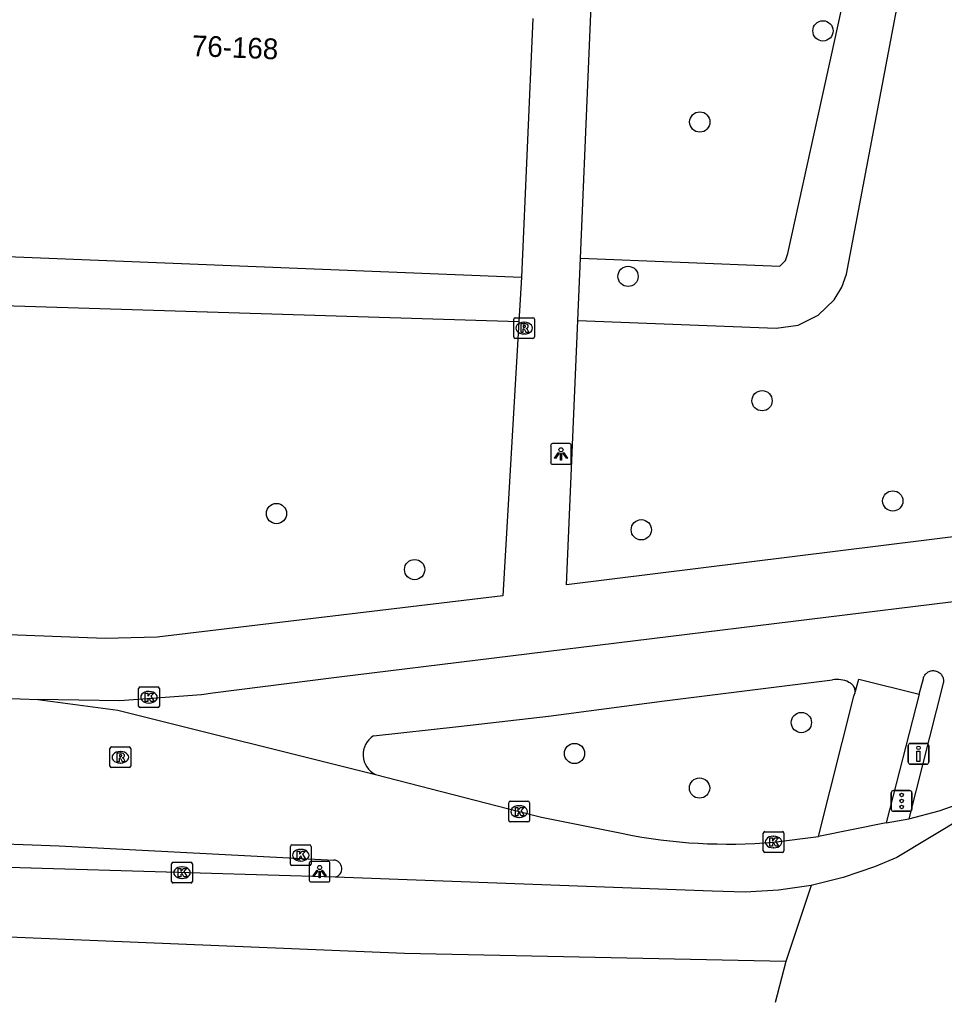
# Model space of a CAD drawing. Extents: x 161253 to 161848, y 384872 to 385383.
# Drawn here: x 161691.79 to 161736.4, y 384872.21 to 384919.64 of the extents above; entities that cross this region are included whole.
import ezdxf

# ---------------------------------------------------------------- set-up
doc = ezdxf.new("R2010")
doc.units = 0
for name, color, linetype in [('IMGEO_Boom', 7, 'Continuous'), ('IMGEO_Drukknoppaal', 7, 'Continuous'), ('IMGEO_Groenvoorziening', 7, 'Continuous'), ('IMGEO_Kolk', 7, 'Continuous'), ('IMGEO_Lichtpunt', 7, 'Continuous'), ('IMGEO_Pand', 7, 'Continuous'), ('IMGEO_Pand_nummerreeks', 7, 'Continuous'), ('IMGEO_Rijbaan_lokaal_open', 7, 'Continuous'), ('IMGEO_Rijbaan_regionaal_gesloten', 7, 'Continuous'), ('IMGEO_Rioolput', 7, 'Continuous'), ('IMGEO_Verkeersregelinstallatiepaal', 7, 'Continuous'), ('IMGEO_Voetpad_gesloten', 7, 'Continuous'), ('IMGEO_Voetpad_open', 7, 'Continuous')]:
    doc.layers.add(name, color=color, linetype=linetype)

msp = doc.modelspace()

# ---------------------------------------------------------------- linework, layer by layer
at = {"layer": 'IMGEO_Boom'}
for centre in [(161730.544, 384919.094), (161724.601, 384914.698), (161721.141, 384907.247), (161727.606, 384901.246), (161733.913, 384896.406), (161704.18, 384895.799), (161721.78, 384895.018), (161710.846, 384893.095), (161729.501, 384885.713), (161718.558, 384884.22), (161724.59, 384882.552)]:
    msp.add_circle(centre, 0.489, dxfattribs=at)
at = {"layer": 'IMGEO_Drukknoppaal'}
for p, q in [((161734.755, 384884.702), (161735.545, 384884.702)), ((161735.545, 384884.702), (161734.755, 384884.702)), ((161734.655, 384883.802), (161734.655, 384884.602)), ((161734.655, 384884.602), (161734.655, 384883.802)), ((161735.645, 384884.602), (161735.645, 384883.802)), ((161735.645, 384883.802), (161735.645, 384884.602)), ((161735.545, 384883.702), (161734.755, 384883.702)), ((161734.755, 384883.702), (161735.545, 384883.702))]:
    msp.add_line(p, q, dxfattribs=at)
msp.add_lwpolyline([(161735.225, 384884.327), (161735.225, 384883.827), (161735.075, 384883.827), (161735.075, 384884.327), (161735.225, 384884.327)], dxfattribs=at)
msp.add_circle((161735.15, 384884.492), 0.085, dxfattribs=at)
for centre, start, end in [((161734.755, 384884.602), 90, 180), ((161734.755, 384884.602), 90, 180), ((161735.545, 384884.602), 0, 90), ((161735.545, 384884.602), 360, 90), ((161734.755, 384883.802), 180, 270), ((161734.755, 384883.802), 180, 270), ((161735.545, 384883.802), 270, 0), ((161735.545, 384883.802), 270, 0)]:
    msp.add_arc(centre, 0.1, start, end, dxfattribs=at)
at = {"layer": 'IMGEO_Groenvoorziening'}
for points in [[(161718.843, 384908.119), (161728.459, 384907.746), (161728.73, 384908.015), (161728.849, 384908.352), (161732.373, 384924.372)], [(161718.716, 384905.121), (161728.292, 384904.75), (161729.354, 384904.9), (161730.318, 384905.37), (161731.089, 384906.116), (161731.458, 384906.73), (161731.678, 384907.354), (161734.799, 384923.838)], [(161715.871, 384905.05), (161685.799, 384905.981)]]:
    msp.add_lwpolyline(points, dxfattribs=at)
at = {"layer": 'IMGEO_Kolk'}
for p, q in [((161697.529, 384886.507), (161697.529, 384887.359)), ((161697.604, 384887.433), (161698.456, 384887.433)), ((161698.017, 384887.213), (161698.042, 384887.213)), ((161698.53, 384887.359), (161698.53, 384886.507)), ((161698.04, 384886.653), (161698.015, 384886.653)), ((161698.456, 384886.433), (161697.604, 384886.433)), ((161715.385, 384880.99), (161715.385, 384881.842)), ((161715.46, 384881.916), (161716.312, 384881.916)), ((161716.386, 384881.842), (161716.386, 384880.99)), ((161715.873, 384881.696), (161715.898, 384881.696)), ((161716.312, 384880.916), (161715.46, 384880.916)), ((161715.896, 384881.136), (161715.871, 384881.136)), ((161727.736, 384880.446), (161728.588, 384880.446)), ((161727.661, 384879.52), (161727.661, 384880.372)), ((161728.149, 384880.226), (161728.174, 384880.226)), ((161728.662, 384880.372), (161728.662, 384879.52)), ((161704.85, 384878.884), (161704.85, 384879.736)), ((161704.925, 384879.81), (161705.777, 384879.81)), ((161705.338, 384879.59), (161705.363, 384879.59)), ((161705.851, 384879.736), (161705.851, 384878.884)), ((161728.588, 384879.446), (161727.736, 384879.446)), ((161728.172, 384879.666), (161728.147, 384879.666)), ((161699.196, 384878.969), (161700.048, 384878.969)), ((161705.361, 384879.03), (161705.336, 384879.03)), ((161699.121, 384878.043), (161699.121, 384878.895)), ((161699.609, 384878.749), (161699.634, 384878.749)), ((161700.122, 384878.895), (161700.122, 384878.043)), ((161705.777, 384878.81), (161704.925, 384878.81)), ((161699.632, 384878.189), (161699.607, 384878.189)), ((161700.048, 384877.969), (161699.196, 384877.969))]:
    msp.add_line(p, q, dxfattribs=at)
for points in [[(161697.529, 384886.507), (161697.529, 384887.359)], [(161697.604, 384887.433), (161698.456, 384887.433)], [(161697.85, 384887.133), (161697.973, 384887.133), (161697.973, 384886.982), (161698.103, 384887.133), (161698.267, 384887.133), (161698.121, 384886.982), (161698.274, 384886.733), (161698.122, 384886.733), (161698.037, 384886.897), (161697.973, 384886.83), (161697.973, 384886.733), (161697.85, 384886.733), (161697.85, 384887.133)], [(161698.53, 384887.359), (161698.53, 384886.507)], [(161698.456, 384886.433), (161697.604, 384886.433)], [(161715.385, 384880.99), (161715.385, 384881.842)], [(161715.46, 384881.916), (161716.312, 384881.916)], [(161716.386, 384881.842), (161716.386, 384880.99)], [(161715.706, 384881.616), (161715.829, 384881.616), (161715.829, 384881.465), (161715.959, 384881.616), (161716.123, 384881.616), (161715.977, 384881.465), (161716.13, 384881.216), (161715.978, 384881.216), (161715.893, 384881.38), (161715.829, 384881.313), (161715.829, 384881.216), (161715.706, 384881.216), (161715.706, 384881.616)], [(161716.312, 384880.916), (161715.46, 384880.916)], [(161727.736, 384880.446), (161728.588, 384880.446)], [(161727.661, 384879.52), (161727.661, 384880.372)], [(161727.982, 384880.146), (161728.105, 384880.146), (161728.105, 384879.995), (161728.235, 384880.146), (161728.399, 384880.146), (161728.253, 384879.995), (161728.406, 384879.746), (161728.254, 384879.746), (161728.169, 384879.91), (161728.105, 384879.843), (161728.105, 384879.746), (161727.982, 384879.746), (161727.982, 384880.146)], [(161728.662, 384880.372), (161728.662, 384879.52)], [(161704.85, 384878.884), (161704.85, 384879.736)], [(161704.925, 384879.81), (161705.777, 384879.81)], [(161705.171, 384879.51), (161705.294, 384879.51), (161705.294, 384879.359), (161705.424, 384879.51), (161705.588, 384879.51), (161705.442, 384879.359), (161705.595, 384879.11), (161705.443, 384879.11), (161705.358, 384879.274), (161705.294, 384879.207), (161705.294, 384879.11), (161705.171, 384879.11), (161705.171, 384879.51)], [(161705.851, 384879.736), (161705.851, 384878.884)], [(161728.588, 384879.446), (161727.736, 384879.446)], [(161699.196, 384878.969), (161700.048, 384878.969)], [(161699.121, 384878.043), (161699.121, 384878.895)], [(161699.442, 384878.669), (161699.565, 384878.669), (161699.565, 384878.518), (161699.695, 384878.669), (161699.859, 384878.669), (161699.713, 384878.518), (161699.866, 384878.269), (161699.714, 384878.269), (161699.629, 384878.433), (161699.565, 384878.366), (161699.565, 384878.269), (161699.442, 384878.269), (161699.442, 384878.669)], [(161700.122, 384878.895), (161700.122, 384878.043)], [(161705.777, 384878.81), (161704.925, 384878.81)], [(161700.048, 384877.969), (161699.196, 384877.969)]]:
    msp.add_lwpolyline(points, dxfattribs=at)
for centre, start, end in [((161697.606, 384887.357), 91.552, 178.448), ((161697.606, 384887.357), 91.552, 178.448), ((161698.454, 384887.357), 1.552, 88.448), ((161698.454, 384887.357), 1.552, 88.448), ((161697.606, 384886.509), 181.552, 268.448), ((161697.606, 384886.509), 181.552, 268.448), ((161698.454, 384886.509), 271.552, 358.448), ((161698.454, 384886.509), 271.552, 358.448), ((161715.462, 384881.84), 91.552, 178.448), ((161715.462, 384881.84), 91.552, 178.448), ((161716.31, 384881.84), 1.552, 88.448), ((161716.31, 384881.84), 1.552, 88.448), ((161715.462, 384880.992), 181.552, 268.448), ((161715.462, 384880.992), 181.552, 268.448), ((161716.31, 384880.992), 271.552, 358.448), ((161716.31, 384880.992), 271.552, 358.448), ((161727.738, 384880.37), 91.552, 178.448), ((161727.738, 384880.37), 91.552, 178.448), ((161728.586, 384880.37), 1.552, 88.448), ((161728.586, 384880.37), 1.552, 88.448), ((161704.927, 384879.734), 91.552, 178.448), ((161704.927, 384879.734), 91.552, 178.448), ((161705.775, 384879.734), 1.552, 88.448), ((161705.775, 384879.734), 1.552, 88.448), ((161727.738, 384879.522), 181.552, 268.448), ((161727.738, 384879.522), 181.552, 268.448), ((161728.586, 384879.522), 271.552, 358.448), ((161728.586, 384879.522), 271.552, 358.448), ((161699.198, 384878.893), 91.552, 178.448), ((161699.198, 384878.893), 91.552, 178.448), ((161700.046, 384878.893), 1.552, 88.448), ((161700.046, 384878.893), 1.552, 88.448), ((161704.927, 384878.886), 181.552, 268.448), ((161704.927, 384878.886), 181.552, 268.448), ((161705.775, 384878.886), 271.552, 358.448), ((161705.775, 384878.886), 271.552, 358.448), ((161699.198, 384878.045), 181.552, 268.448), ((161699.198, 384878.045), 181.552, 268.448), ((161700.046, 384878.045), 271.552, 358.448), ((161700.046, 384878.045), 271.552, 358.448)]:
    msp.add_arc(centre, 0.0765, start, end, dxfattribs=at)
for centre, major_axis, ratio, start_param, end_param in [((161698.016, 384886.933), (-0.387, 0.002), 0.722429, 4.712389, 7.853982), ((161698.041, 384886.933), (-0.39, 0.002), 0.717154, 1.570796, 4.712389), ((161715.872, 384881.416), (-0.387, 0.002), 0.722429, 4.712389, 7.853982), ((161715.897, 384881.416), (-0.39, 0.002), 0.717154, 1.570796, 4.712389), ((161728.148, 384879.946), (-0.387, 0.002), 0.722429, 4.712389, 7.853982), ((161728.173, 384879.946), (-0.39, 0.002), 0.717154, 1.570796, 4.712389), ((161705.337, 384879.31), (-0.387, 0.002), 0.722429, 4.712389, 7.853982), ((161705.362, 384879.31), (-0.39, 0.002), 0.717154, 1.570796, 4.712389), ((161699.608, 384878.469), (-0.387, 0.002), 0.722429, 4.712389, 7.853982), ((161699.633, 384878.469), (-0.39, 0.002), 0.717154, 1.570796, 4.712389)]:
    msp.add_ellipse(centre, major_axis=major_axis, ratio=ratio, start_param=start_param, end_param=end_param, dxfattribs=at)
at = {"layer": 'IMGEO_Lichtpunt'}
for p, q in [((161717.408, 384899.079), (161717.408, 384898.272)), ((161717.408, 384899.079), (161717.408, 384898.272)), ((161718.31, 384899.174), (161717.502, 384899.174)), ((161718.31, 384899.174), (161717.502, 384899.174)), ((161718.404, 384898.272), (161718.404, 384899.079)), ((161718.404, 384898.272), (161718.404, 384899.079)), ((161717.502, 384898.178), (161718.31, 384898.178)), ((161717.502, 384898.178), (161718.31, 384898.178)), ((161706.665, 384879.014), (161705.857, 384879.014)), ((161706.665, 384879.014), (161705.857, 384879.014)), ((161705.763, 384878.919), (161705.763, 384878.112)), ((161705.763, 384878.919), (161705.763, 384878.112)), ((161706.759, 384878.112), (161706.759, 384878.919)), ((161706.759, 384878.112), (161706.759, 384878.919)), ((161705.857, 384878.018), (161706.665, 384878.018)), ((161705.857, 384878.018), (161706.665, 384878.018))]:
    msp.add_line(p, q, dxfattribs=at)
for points in [[(161717.782, 384898.743), (161717.821, 384898.715), (161717.633, 384898.453), (161717.595, 384898.48), (161717.782, 384898.743)], [(161717.884, 384898.695), (161717.931, 384898.695), (161717.931, 384898.373), (161717.884, 384898.373), (161717.884, 384898.695)], [(161717.994, 384898.715), (161718.032, 384898.742), (161718.219, 384898.48), (161718.18, 384898.452), (161717.994, 384898.715)], [(161706.137, 384878.583), (161706.176, 384878.555), (161705.988, 384878.293), (161705.95, 384878.32), (161706.137, 384878.583)], [(161706.239, 384878.535), (161706.286, 384878.535), (161706.286, 384878.213), (161706.239, 384878.213), (161706.239, 384878.535)], [(161706.349, 384878.555), (161706.387, 384878.582), (161706.574, 384878.32), (161706.535, 384878.292), (161706.349, 384878.555)]]:
    msp.add_lwpolyline(points, dxfattribs=at)
for centre in [(161717.907, 384898.877), (161706.262, 384878.717)]:
    msp.add_circle(centre, 0.0994, dxfattribs=at)
for centre, start, end in [((161717.502, 384899.079), 90, 180), ((161717.502, 384899.079), 90, 180), ((161718.31, 384899.079), 0, 90), ((161718.31, 384899.079), 0, 90), ((161717.502, 384898.272), 180, 270), ((161717.502, 384898.272), 180, 270), ((161718.31, 384898.272), 270, 0), ((161718.31, 384898.272), 270, 360), ((161705.857, 384878.919), 90, 180), ((161705.857, 384878.919), 90, 180), ((161706.665, 384878.919), 0, 90), ((161706.665, 384878.919), 0, 90), ((161705.857, 384878.112), 180, 270), ((161705.857, 384878.112), 180, 270), ((161706.665, 384878.112), 270, 0), ((161706.665, 384878.112), 270, 360)]:
    msp.add_arc(centre, 0.0946, start, end, dxfattribs=at)
at = {"layer": 'IMGEO_Pand'}
for points in [[(161716.555, 384919.692), (161715.997, 384907.204)], [(161689.171, 384908.286), (161715.997, 384907.204)]]:
    msp.add_lwpolyline(points, dxfattribs=at)
at = {"layer": 'IMGEO_Rijbaan_lokaal_open'}
for points in [[(161662.403, 384887.976), (161663.754, 384887.928), (161666.228, 384887.818), (161692.66, 384886.829)], [(161692.66, 384886.829), (161696.52, 384886.316), (161708.962, 384883.201)], [(161734.693, 384881.066), (161736.146, 384881.444), (161737.56, 384881.951), (161738.922, 384882.582), (161740.223, 384883.332), (161741.028, 384883.879)], [(161708.962, 384883.201), (161715.882, 384881.415), (161716.973, 384881.138), (161720.912, 384880.351)], [(161662.143, 384880.926), (161667.54, 384880.734), (161693.704, 384879.755), (161706.945, 384879.077)], [(161733.587, 384880.868), (161730.33, 384880.216)], [(161733.587, 384880.868), (161734.693, 384881.066)], [(161728.163, 384879.945), (161730.33, 384880.216)]]:
    msp.add_lwpolyline(points, dxfattribs=at)
for centre, radius, start, end in [((161725.935, 384905.102), 25.256, 258.5288, 275.0616), ((161706.915, 384878.659), 0.419, 284.714, 85.838)]:
    msp.add_arc(centre, radius, start, end, dxfattribs=at)
at = {"layer": 'IMGEO_Rijbaan_regionaal_gesloten'}
for points in [[(161741.028, 384883.879), (161740.405, 384883.372), (161737.347, 384881.144), (161734.102, 384879.199), (161733.037, 384878.743), (161731.524, 384878.23), (161729.972, 384877.854)], [(161707.021, 384878.254), (161684.154, 384878.919), (161672.75, 384879.376), (161659.227, 384879.962), (161648.353, 384880.446)], [(161728.753, 384874.183), (161710.356, 384874.561), (161646.491, 384877.202), (161622.338, 384877.882), (161608.73, 384878.956), (161597.451, 384878.956), (161580.262, 384879.852), (161565.402, 384878.956), (161563.138, 384878.938)], [(161729.972, 384877.854), (161728.392, 384877.617), (161726.797, 384877.523), (161725.2, 384877.572), (161707.021, 384878.254)], [(161729.972, 384877.854), (161728.753, 384874.183)], [(161728.753, 384874.183), (161728.756, 384874.183), (161728.245, 384872.208)]]:
    msp.add_lwpolyline(points, dxfattribs=at)
at = {"layer": 'IMGEO_Rioolput'}
for p, q in [((161715.627, 384904.325), (161715.627, 384905.177)), ((161715.702, 384905.251), (161716.554, 384905.251)), ((161716.628, 384905.177), (161716.628, 384904.325)), ((161716.115, 384905.031), (161716.14, 384905.031)), ((161716.554, 384904.251), (161715.702, 384904.251)), ((161716.138, 384904.471), (161716.113, 384904.471)), ((161696.148, 384883.61), (161696.148, 384884.462)), ((161696.223, 384884.536), (161697.075, 384884.536)), ((161696.636, 384884.316), (161696.661, 384884.316)), ((161697.149, 384884.462), (161697.149, 384883.61)), ((161696.659, 384883.756), (161696.634, 384883.756)), ((161697.075, 384883.536), (161696.223, 384883.536))]:
    msp.add_line(p, q, dxfattribs=at)
for points in [[(161715.627, 384904.325), (161715.627, 384905.177)], [(161715.702, 384905.251), (161716.554, 384905.251)], [(161716.628, 384905.177), (161716.628, 384904.325)], [(161716.216, 384904.949), (161715.964, 384904.951), (161715.964, 384904.551)], [(161715.964, 384904.551), (161716.088, 384904.551), (161716.088, 384904.713), (161716.099, 384904.713)], [(161716.142, 384904.87), (161716.088, 384904.87), (161716.088, 384904.789)], [(161716.088, 384904.789), (161716.14, 384904.789)], [(161716.146, 384904.684), (161716.217, 384904.551), (161716.357, 384904.551), (161716.292, 384904.677)], [(161716.554, 384904.251), (161715.702, 384904.251)], [(161696.148, 384883.61), (161696.148, 384884.462)], [(161696.223, 384884.536), (161697.075, 384884.536)], [(161696.737, 384884.234), (161696.485, 384884.236), (161696.485, 384883.836)], [(161697.149, 384884.462), (161697.149, 384883.61)], [(161696.485, 384883.836), (161696.609, 384883.836), (161696.609, 384883.998), (161696.62, 384883.998)], [(161696.663, 384884.155), (161696.609, 384884.155), (161696.609, 384884.074)], [(161696.609, 384884.074), (161696.661, 384884.074)], [(161696.667, 384883.969), (161696.738, 384883.836), (161696.878, 384883.836), (161696.813, 384883.962)], [(161697.075, 384883.536), (161696.223, 384883.536)]]:
    msp.add_lwpolyline(points, dxfattribs=at)
for centre, radius, start, end in [((161715.704, 384905.175), 0.0765, 91.552, 178.448), ((161715.704, 384905.175), 0.0765, 91.552, 178.448), ((161716.552, 384905.175), 0.0765, 1.552, 88.448), ((161716.552, 384905.175), 0.0765, 1.552, 88.448), ((161716.098, 384904.66), 0.0533, 26.0293, 88.6989), ((161716.124, 384904.978), 0.19, 274.7715, 282.9687), ((161716.148, 384904.774), 0.0964, 77.0061, 93.1865), ((161716.162, 384904.831), 0.0378, 276.6634, 79.6772), ((161716.215, 384904.839), 0.109, 350.3612, 89.416), ((161716.213, 384904.839), 0.112, 277.5842, 350.9817), ((161716.197, 384904.624), 0.108, 29.5134, 73.7905), ((161715.704, 384904.327), 0.0765, 181.552, 268.448), ((161715.704, 384904.327), 0.0765, 181.552, 268.448), ((161716.552, 384904.327), 0.0765, 271.552, 358.448), ((161716.552, 384904.327), 0.0765, 271.552, 358.448), ((161696.225, 384884.46), 0.0765, 91.552, 178.448), ((161696.225, 384884.46), 0.0765, 91.552, 178.448), ((161696.736, 384884.124), 0.109, 350.3612, 89.416), ((161697.073, 384884.46), 0.0765, 1.552, 88.448), ((161697.073, 384884.46), 0.0765, 1.552, 88.448), ((161696.619, 384883.945), 0.0533, 26.0293, 88.6989), ((161696.645, 384884.263), 0.19, 274.7715, 282.9687), ((161696.669, 384884.059), 0.0964, 77.0061, 93.1865), ((161696.683, 384884.116), 0.0378, 276.6634, 79.6772), ((161696.734, 384884.124), 0.112, 277.5842, 350.9817), ((161696.718, 384883.909), 0.108, 29.5134, 73.7905), ((161696.225, 384883.612), 0.0765, 181.552, 268.448), ((161696.225, 384883.612), 0.0765, 181.552, 268.448), ((161697.073, 384883.612), 0.0765, 271.552, 358.448), ((161697.073, 384883.612), 0.0765, 271.552, 358.448)]:
    msp.add_arc(centre, radius, start, end, dxfattribs=at)
for centre, major_axis, ratio, start_param, end_param in [((161716.114, 384904.751), (-0.387, 0.002), 0.722429, 4.712389, 7.853982), ((161716.139, 384904.751), (-0.39, 0.002), 0.717154, 1.570796, 4.712389), ((161696.635, 384884.036), (-0.387, 0.002), 0.722429, 4.712389, 7.853982), ((161696.66, 384884.036), (-0.39, 0.002), 0.717154, 1.570796, 4.712389)]:
    msp.add_ellipse(centre, major_axis=major_axis, ratio=ratio, start_param=start_param, end_param=end_param, dxfattribs=at)
at = {"layer": 'IMGEO_Verkeersregelinstallatiepaal'}
for p, q in [((161733.842, 384881.528), (161733.842, 384882.328)), ((161733.842, 384882.328), (161733.842, 384881.528)), ((161733.942, 384882.428), (161734.732, 384882.428)), ((161734.732, 384882.428), (161733.942, 384882.428)), ((161734.832, 384882.328), (161734.832, 384881.528)), ((161734.832, 384881.528), (161734.832, 384882.328)), ((161734.732, 384881.428), (161733.942, 384881.428)), ((161733.942, 384881.428), (161734.732, 384881.428))]:
    msp.add_line(p, q, dxfattribs=at)
for centre in [(161734.337, 384882.218), (161734.337, 384881.928), (161734.337, 384881.638)]:
    msp.add_circle(centre, 0.085, dxfattribs=at)
for centre, start, end in [((161733.942, 384882.328), 90, 180), ((161733.942, 384882.328), 90, 180), ((161734.732, 384882.328), 0, 90), ((161734.732, 384882.328), 360, 90), ((161733.942, 384881.528), 180, 270), ((161733.942, 384881.528), 180, 270), ((161734.732, 384881.528), 270, 0), ((161734.732, 384881.528), 270, 0)]:
    msp.add_arc(centre, 0.1, start, end, dxfattribs=at)
at = {"layer": 'IMGEO_Voetpad_gesloten'}
for points in [[(161737.507, 384891.623), (161707.082, 384887.89), (161701.116, 384887.126), (161700.566, 384887.057), (161696.618, 384886.766), (161692.66, 384886.829)], [(161735.193, 384887.09), (161735.387, 384887.842), (161735.401, 384887.889), (161735.417, 384887.93), (161735.437, 384887.969), (161735.461, 384888.007), (161735.487, 384888.042), (161735.517, 384888.074), (161735.55, 384888.104), (161735.585, 384888.131), (161735.622, 384888.154), (161735.661, 384888.174), (161735.702, 384888.191), (161735.744, 384888.203), (161735.787, 384888.212), (161735.831, 384888.218), (161735.875, 384888.219), (161735.919, 384888.216), (161735.962, 384888.209), (161736.005, 384888.199), (161736.046, 384888.184), (161736.087, 384888.166), (161736.125, 384888.145), (161736.161, 384888.12), (161736.195, 384888.092), (161736.227, 384888.061), (161736.255, 384888.027), (161736.28, 384887.991), (161736.302, 384887.953), (161736.321, 384887.913), (161736.336, 384887.872), (161736.347, 384887.829), (161736.354, 384887.786), (161736.357, 384887.742), (161736.357, 384887.698), (161736.352, 384887.654), (161736.344, 384887.611), (161734.693, 384881.066)], [(161708.857, 384885.071), (161712.964, 384885.53), (161717.311, 384886.019), (161722.902, 384886.762), (161731.009, 384887.772)], [(161731.781, 384887.665), (161731.795, 384887.659), (161731.834, 384887.64), (161731.872, 384887.617), (161731.907, 384887.59), (161731.94, 384887.561), (161731.97, 384887.529), (161731.997, 384887.494), (161732.02, 384887.457), (161732.041, 384887.419), (161732.058, 384887.378), (161732.071, 384887.336), (161732.08, 384887.293), (161732.086, 384887.25), (161732.087, 384887.206), (161732.085, 384887.162), (161732.079, 384887.119)], [(161732.079, 384887.119), (161732.274, 384887.806), (161735.193, 384887.09)]]:
    msp.add_lwpolyline(points, dxfattribs=at)
for centre, radius, start, end in [((161731.225, 384886.495), 1.295, 64.593, 99.6251), ((161709.434, 384884.165), 1.074, 122.5093, 243.9183)]:
    msp.add_arc(centre, radius, start, end, dxfattribs=at)
at = {"layer": 'IMGEO_Voetpad_open'}
for points in [[(161718.843, 384908.119), (161719.586, 384925.643)], [(161749.286, 384920.651), (161747.988, 384914.506), (161746.927, 384909.981), (161745.225, 384904.716), (161743.858, 384901.082), (161742.751, 384898.726), (161742.526, 384898.315), (161742.156, 384897.746), (161741.736, 384897.213), (161741.271, 384896.72), (161740.763, 384896.27), (161740.218, 384895.867), (161739.638, 384895.514), (161739.029, 384895.215), (161738.396, 384894.971), (161737.744, 384894.785), (161718.175, 384892.354), (161718.716, 384905.121)], [(161718.716, 384905.121), (161718.843, 384908.119)], [(161715.997, 384907.204), (161715.871, 384905.05)], [(161715.871, 384905.05), (161715.097, 384891.825), (161698.423, 384889.831), (161695.922, 384889.765), (161660.772, 384891.099), (161660.581, 384891.113), (161660.305, 384891.155), (161660.034, 384891.221), (161659.77, 384891.311), (161659.515, 384891.424)], [(161730.33, 384880.216), (161732.037, 384886.994), (161732.055, 384887.034), (161732.068, 384887.076), (161732.079, 384887.119)], [(161735.193, 384887.09), (161733.587, 384880.868)]]:
    msp.add_lwpolyline(points, dxfattribs=at)

# ---------------------------------------------------------------- texts
at = {"layer": 'IMGEO_Pand_nummerreeks'}
msp.add_text('76-168', height=1, rotation=357.682, dxfattribs=at).set_placement((161700.086, 384917.885))

doc.saveas('drawing.dxf')
